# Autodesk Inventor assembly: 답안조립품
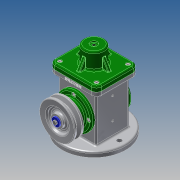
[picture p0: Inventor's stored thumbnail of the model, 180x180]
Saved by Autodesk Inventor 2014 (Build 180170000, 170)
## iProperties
Created: 2018-10
Part Number: 답안조립품
Document SubType Name: Assembly
Designer: net
Author: net
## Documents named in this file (18)
- C:\Users\net\Desktop\481007V1067\답안조립품.iam
- C:\Users\net\Desktop\481007V1067\답안본체.ipt
- C:\Users\net\Desktop\481007V1067\편심축.ipt
- C:\Users\net\Desktop\481007V1067\베어링 17 x 40 x 12.ipt
- C:\Users\net\Desktop\481007V1067\앞커버.ipt
- C:\Users\net\Desktop\481007V1067\뒤커버.ipt
- C:\Users\net\Desktop\481007V1067\오일 실 17 30 8.ipt
- C:\Users\net\Desktop\481007V1067\키 4 x 4 x 12.ipt
- C:\Users\net\Desktop\481007V1067\V-벨트풀리.ipt
- C:\Users\net\Desktop\481007V1067\볼트 M4 x 10.ipt
- C:\Users\net\Desktop\481007V1067\와셔 4x16.ipt
- C:\Users\net\Desktop\481007V1067\링크.ipt
- C:\Users\net\Desktop\481007V1067\클레비스 핀 6 x 22.ipt
- 클레비스 핀 6 x 22.ipt
- C:\Users\net\Desktop\481007V1067\슬라이더.ipt
- C:\Users\net\Desktop\481007V1067\덮개.ipt
- C:\Users\net\Desktop\481007V1067\E-링.ipt
- C:\Users\net\Desktop\481007V1067\볼트 M4 x 8.ipt
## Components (2 placed, 2 different names)
1. V-벨트풀리:1
2. E-링:1
